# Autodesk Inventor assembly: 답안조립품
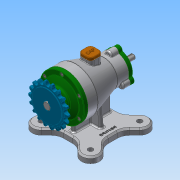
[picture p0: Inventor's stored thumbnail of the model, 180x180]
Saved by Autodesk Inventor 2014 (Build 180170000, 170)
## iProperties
Created: 2018-03
Part Number: 답안조립품
Document SubType Name: Assembly
Designer: user
Author: user
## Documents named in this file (15)
- C:\Users\user\Desktop\480307V1018\답안조립품.iam
- C:\Users\user\Desktop\480307V1018\본체.ipt
- C:\Users\user\Desktop\480307V1018\뒤커버.ipt
- C:\Users\user\Desktop\480307V1018\마개.ipt
- C:\Users\user\Desktop\480307V1018\베어링-6200.ipt
- C:\Users\user\Desktop\480307V1018\베어링-6203.ipt
- C:\Users\user\Desktop\480307V1018\볼트 M4 x 12.ipt
- 볼트 M4 x 12.ipt
- C:\Users\user\Desktop\480307V1018\스프로킷.ipt
- C:\Users\user\Desktop\480307V1018\앞커버.ipt
- C:\Users\user\Desktop\480307V1018\오일 실 10 20 7.ipt
- C:\Users\user\Desktop\480307V1018\오일 실 17 30 8.ipt
- C:\Users\user\Desktop\480307V1018\축.ipt
- C:\Users\user\Desktop\480307V1018\키 5 x 5.ipt
- 키 5 x 5.ipt
